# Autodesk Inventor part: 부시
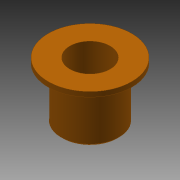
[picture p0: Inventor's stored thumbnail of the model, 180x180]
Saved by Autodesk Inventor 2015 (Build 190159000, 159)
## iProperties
Created: 2015-10
Part Number: 부시
Document SubType Name: Modeling
Designer: mdu
Density: 7.86 g/cm^3
Material: 황동, 연질
Mass: 246.97 g
Surface Area: 129.264 cm^2
Volume: 31.4212 cm^3
Appearance: 주황색
Author: mdu
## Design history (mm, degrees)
sketch "스케치1"
  geometry: C1 r 31 at (0, 0) reference; C2 r 25 at (0, 0) reference; C3 r 30 at (0, 0) reference; C4 r 26 at (0, 0); C5 r 18 at (0, 0); 1 further point
  constraints: 2 centre point, 2 coincident
  dimensions: "d20" = 5 radial gap between concentric circles of C1 C4; "d21" = 8 radial gap between concentric circles of C5 C4
  node "참조1"
  node "참조2"
  node "참조4"
extrude "돌출1" new body sketch "스케치1" distance "d0" = 10; taper "d1" = 0 deg
extrude "돌출2" join sketch "스케치1" distance "d2" = 35; taper "d3" = 0 deg
sketch "스케치4"
  geometry: C1 r 12.5 at (0, 0); 1 further point
  constraints: 1 centre point, 1 coincident
  dimensions: "d24" = 25 diameter of C1
extrude "돌출5" cut sketch "스케치4" stored distance "d25" = 10; taper "d26" = 0 deg
chamfer "모따기1" distance "d6" = 1; stored, may be unused: second distance "d7" = 2, angle "d8" = 45 deg
node "솔리드1"
